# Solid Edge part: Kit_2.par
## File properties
Dokumentum tartalom típus: 0
Last saved by: ahadarics
Revision: 76
Sűrűség: 0,000 kg/m^3
Pontosság: 0,990
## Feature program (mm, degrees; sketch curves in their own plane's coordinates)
base feature "unnamed BaseFeature 1"
sketch for "unnamed Hole 1" plane through (-23.25, 23.25, 5) normal (0, 0, -1) x-axis (0, -1, 0)
hole "unnamed Hole 1" through
sketch for "unnamed Hole 2" plane through (-23.25, 23.25, 5) normal (0, 0, -1) x-axis (0, -1, 0)
  hole centre (46.5, 0) bore radius 3.3235
hole "unnamed Hole 2" through
sketch for "unnamed Hole 3" plane through (-23.25, 23.25, 5) normal (0, 0, -1) x-axis (0, -1, 0)
  hole centre (46.5, -46.5) bore radius 3.3235
hole "unnamed Hole 3" through
sketch for "unnamed Hole 4" plane through (-23.25, 23.25, 5) normal (0, 0, -1) x-axis (0, -1, 0)
  hole centre (0, -46.5) bore radius 3.3235
hole "unnamed Hole 4" through
pattern "unnamed Pattern 1" of "unnamed Hole 1", "unnamed Hole 2", "unnamed Hole 3", "unnamed Hole 4"
sketch for "Furat_5" plane through (-32.6867, 0, 7.25) normal (-0.999962, 0, -0.008727) x-axis (0, -1, 0)
  hole centre (0.0005, 0.7497) bore radius 4.283
  dimension (linear) = 0.0005
hole "Furat_5" diameter 8.566 finite
thread "unnamed Thread 1"
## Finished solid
Body 1: solid body, 302 faces, 741 edges, 459 vertices, 4 internal voids.
  Faces by surface: plane 139, cylinder 78, swept 53, torus 20, cone 11, spline 1
  Edges by curve: line 413, circle 160, spline 122, ellipse 28, curve on surface 18
Bounding box of the edges (mm; curved faces can reach further): 65.500 x 65.500 x 14.500, from (-32.75, -32.75, 0) to (32.75, 32.75, 14.5).
Cylindrical faces by radius (mm): R0.2 x40, R0.201 x2, R0.2012 x2, R2.5402 x12, R2.6 x4, R3.3235 x4, R3.75 x4, R3.85 x4, R4.283 x1, R5.25 x4, R6 x1
Conical faces (half-angle, radius in mm at the cone's reference point): 0.5 deg R6.5 x2, 0.5 deg R8 x4, 45 deg R3.6735 x4, 45 deg R6.15 x1
Toroidal faces (ring radius, tube radius in mm): R2.9402 r0.4 x12, R3.55 r0.2 x8
Planar faces by outward normal: +x 11, +y 12, +z 1, -x 12, -y 12, -z 22, oblique 69
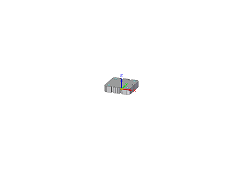
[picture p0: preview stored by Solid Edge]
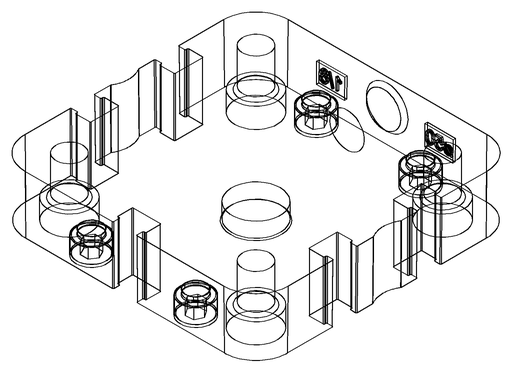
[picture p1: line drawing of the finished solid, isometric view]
